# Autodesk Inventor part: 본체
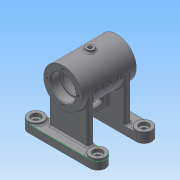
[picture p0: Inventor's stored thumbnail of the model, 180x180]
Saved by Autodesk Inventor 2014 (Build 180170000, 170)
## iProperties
Created: 2015-11
Part Number: 본체
Material: 일반
Document SubType Name: Modeling
Designer: net
Density: 1 g/cm^3
Appearance: 기본값
Author: net
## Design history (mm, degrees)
sketch "스케치1"
  geometry: L1 (-40, -10)-(40, -10); L2 (40, 10)-(-40, 10); L3 (-40, -10)-(35.294, 8.824); L4 (40, -10)-(-40, 10); C1 r 3 at (-40, 0); C2 r 3 at (40, 0); A1 r 10 centre (-40, 0) between (-40, 10) and (-40, -10); A2 r 10 centre (40, 0) between (40, -10) and (40, 10); 1 further point
  constraints: 8 end point, 4 centre point, 4 point on circle, 2 coincident, 2 equal radius, 2 parallel, 2 tangent, 1 horizontal, 1 midpoint, 1 point on line
  dimensions: "d15" = 100 dimension on A2 A1; "d18" = 10 radius of A1; "d19" = 6 diameter of C1; "d20" = 151.928 deg angle of L3 L4; "d21" = 17.12016 distance from line of L3.end L4
extrude "돌출1" new body sketch "스케치1" distance "d22" = 10; taper "d23" = 0 deg
sketch "스케치2"
  geometry: C1 r 3 at (40, 0) reference; C2 r 3 at (-40, 0) reference; C3 r 10 at (-40, 0); C4 r 10 at (40, 0); A1 r 10 centre (-40, 0) between (-40, 10) and (-40, -10) reference; A2 r 10 centre (40, 0) between (40, -10) and (40, 10) reference; 1 further point
  constraints: 2 centre point, 2 coincident
  dimensions: "d24" = 20 diameter of C3; "d25" = 20 diameter of C4
extrude "돌출2" join sketch "스케치2" distance "d26" = 3; taper "d27" = 0 deg
sketch "스케치3"
  geometry: L1 (80, 0)-(0, 0) reference; L2 (15, 68)-(65, 68); L3 (65, 68)-(65, 0); L4 (65, 0)-(15, 0); L5 (15, 0)-(15, 68); 2 further points
  constraints: 8 end point, 2 midpoint, 2 parallel, 1 horizontal, 1 perpendicular
  dimensions: "d28" = 50 distance of L3.end L4.end; "d29" = 68 distance between parallel lines of L4 L2
extrude "돌출3" join sketch "스케치3" distance "d30" = 8; taper "d31" = 0 deg
sketch "스케치4"
  geometry: L1 (-40, -50)-(40, -50); L2 (40, -50)-(40, -70); L3 (40, -70)-(-40, -70); L4 (-40, -70)-(-40, -50); C1 r 3 at (-40, -60); C2 r 3 at (40, -60); 3 further points
  constraints: 8 end point, 2 centre point, 2 coincident, 2 midpoint, 2 parallel, 2 vertical alignment, 1 equal radius, 1 horizontal, 1 perpendicular, 4 other
  dimensions: "d34" = 80 distance between parallel lines of L2 L4; "d35" = 20 distance between parallel lines of L3 L1; "d36" = 40 distance from line of point (0, 0) L4 (= 0.5 x d34); "d37" = 50 distance from line of L1 point (0, 0); "d38" = 6 diameter of C1
extrude "돌출4" join sketch "스케치4" distance "d39" = 10; taper "d40" = 0 deg
sketch "스케치5"
  geometry: L1 (-40, -70)-(40, -70) reference; L2 (40, -50)-(-40, -50) reference; A1 r 10 centre (40, -60) between (40, -70) and (40, -50) reference; A2 r 10 centre (-40, -60) between (-40, -50) and (-40, -70) reference; 1 further point
extrude "돌출5" join sketch "스케치4" distance "d41" = 13; taper "d42" = 0 deg
extrude "돌출6" cut sketch "스케치4" stored distance "d43" = 13; taper "d44" = 0 deg
sketch "스케치6"
  geometry: L1 (0, 0)-(80, 0) reference; L2 (15, -68)-(65, -68); L3 (65, -68)-(65, 0); L4 (65, 0)-(15, 0); L5 (15, 0)-(15, -68); 1 further point
  constraints: 8 end point, 2 parallel, 1 horizontal, 1 perpendicular, 1 point on line
  dimensions: "d45" = 50 distance between parallel lines of L3 L5; "d46" = 68 distance between parallel lines of L2 L1; "d47" = 25 distance from line of point (40, 0) L5 (= 0.5 x d45)
extrude "돌출7" join sketch "스케치6" distance "d48" = 8; taper "d49" = 0 deg
node "작업 평면1"
node "작업 평면2"
sketch "스케치8"
  geometry: L1 (0, -40)-(0, -48) reference; L2 (0, 0)-(0, 8) reference; L3 (-25, -55)-(0, -55); L4 (0, -55)-(0, 15); L5 (0, 15)-(-25, 15); L6 (-25, 15)-(-25, -55); L7 (45, 0)-(45, -40) reference; L8 (45, -20)-(-11.349, -20); L9 (68, -60)-(68, -40) reference; L10 (68, 0)-(68, 20) reference; 2 further points
  constraints: 10 end point, 2 horizontal, 2 midpoint, 2 parallel, 1 perpendicular, 1 point on line
  dimensions: "d60" = 70 distance of L5.end L3.start; "d61" = 25 distance of L3.start L3.end; "d62" = 56.34938 distance of L8.start L8.end; "d64" = 68 distance between parallel lines of L10 L4
revolve "회전1" sketch "스케치8" stored, may be unused: angle "d65" = 90 deg
node "작업 평면3"
sketch "스케치10"
  geometry: L1 (-83, -7)-(-83, 63) reference; L2 (-33, -7)-(-33, 63) reference; L3 (-33, -7)-(-83, -7) reference; L4 (-58, -7)-(-58, 63); L5 (-33, 63)-(-83, 63) reference; L6 (-58, 7)-(-79, 7); L7 (-79, 7)-(-79, 49); L8 (-79, 49)-(-58, 49); 1 further point
  constraints: 8 end point, 2 horizontal, 2 midpoint, 2 point on line, 1 vertical
  dimensions: "d72" = 42 distance between parallel lines of L8 L6; "d73" = 14 distance between parallel lines of L6 L3; "d74" = 42 diameter of L7 L4
revolve "회전2" sketch "스케치10" stored, may be unused: angle "d75" = 90 deg
hole "구멍1" diameter "d78" = 28; stored, may be unused: countersink angle "d82" = 90 deg, drill point angle "d84" = 0 deg; dims "d76" = 10, "d77" = 10, "d79" = 6, "d80" = 32, "d81" = 12, "d83" = 14
hole "구멍2" diameter "d87" = 28; stored, may be unused: countersink angle "d91" = 90 deg, drill point angle "d93" = 0 deg; dims "d85" = 10, "d86" = 10, "d88" = 6, "d89" = 32, "d90" = 12, "d92" = 14
node "작업 평면4"
sketch "스케치11"
  geometry: L1 (0, -50)-(0, -10) reference; C1 r 5 at (0, -30); 1 further point
  constraints: 1 centre point, 1 midpoint
  dimensions: "d95" = 10 diameter of C1
extrude "돌출9" join sketch "스케치11" stored distance "d96" = 8; taper "d97" = 0 deg
node "작업 평면5"
sketch "스케치12"
  geometry: L1 (40, -68)-(15, -68); L2 (40, -68)-(15.751, -54); C1 r 16 at (40, -68) reference; 1 further point
  constraints: 4 end point, 1 horizontal, 1 horizontal alignment
  dimensions: "d98" = 30 deg angle of L2 L1; "d99" = 28 distance of L1.start L2.end
  node "투영된 루프4"
node "작업 평면6"
sketch "스케치13"
  geometry: L1 (-35, 25)-(-35, -25) reference; C1 r 6 at (0, 0); 1 further point
  constraints: 1 centre point
  dimensions: "d100" = 12 diameter of C1; "d101" = 66.09085 distance of C1.centre point (-30, -58.89); "d102" = 35 distance from line of C1.centre L1
extrude "돌출10" join sketch "스케치13" stored distance "d103" = 8; taper "d104" = 0 deg
hole "구멍3" diameter "d107" = 4.917; stored, may be unused: countersink angle "d111" = 90 deg, drill point angle "d113" = 118 deg; dims "d105" = 10, "d106" = 10, "d108" = 6, "d109" = 32, "d110" = 12, "d112" = 14
hole "구멍4" diameter "d116" = 4.917; stored, may be unused: countersink angle "d120" = 90 deg, drill point angle "d122" = 118 deg; dims "d114" = 10, "d115" = 10, "d117" = 6, "d118" = 32, "d119" = 12, "d121" = 14
sketch "스케치14"
  geometry: C1 r 16 at (0, 0) reference; 2 further points
  constraints: 1 vertical alignment
  dimensions: "d123" = 20 distance of C1.centre point (0, 20)
hole "구멍5" sketch "스케치14" at (0, 20) diameter "d124" = 3.242; stored, may be unused: countersink angle "d128" = 90 deg, drill point angle "d130" = 118 deg; dims "d125" = 8, "d126" = 32, "d127" = 12, "d129" = 10
node "작업 평면7"
sketch "스케치15"
  geometry: C1 r 3 at (0, 0) reference; C2 r 10 at (0, 0) reference; 1 further point
hole "구멍6" diameter "d136" = 12; stored, may be unused: countersink angle "d140" = 90 deg, drill point angle "d142" = 0 deg; dims "d134" = 10, "d135" = 10, "d137" = 8, "d138" = 32, "d139" = 12, "d141" = 4
hole "구멍7" diameter "d145" = 12; stored, may be unused: countersink angle "d149" = 90 deg, drill point angle "d151" = 0 deg; dims "d143" = 10, "d144" = 10, "d146" = 8, "d147" = 32, "d148" = 12, "d150" = 4
hole "구멍8" diameter "d154" = 12; stored, may be unused: countersink angle "d158" = 90 deg, drill point angle "d160" = 0 deg; dims "d152" = 10, "d153" = 10, "d155" = 8, "d156" = 32, "d157" = 12, "d159" = 4
hole "구멍9" diameter "d163" = 12; stored, may be unused: countersink angle "d167" = 90 deg, drill point angle "d169" = 0 deg; dims "d161" = 10, "d162" = 10, "d164" = 8, "d165" = 32, "d166" = 12, "d168" = 4
fillet "모깎기1" dims "d170" = 2
fillet "모깎기2" dims "d171" = 2
node "작업 평면8"
sketch "스케치16"
  geometry: L1 (-48.202, 6)-(0, 6) reference; L2 (10, 59)-(10, 53) reference; L3 (10, -1)-(10, -7) reference; L4 (0, 46)-(-48.202, 46) reference; L5 (-35, 6)-(-13, 6); L6 (-13, 6)-(-13, 46); L7 (-13, 46)-(-35, 46); L8 (-35, 46)-(-35, 6); L9 (10, 46)-(10, 66) reference; L10 (-23, 18)-(-23, 34); L11 (-19.5, 18)-(-19.5, 34); L12 (-26.5, 34)-(-26.5, 18); A1 r 3.5 centre (-23, 18) between (-26.5, 18) and (-19.5, 18); A2 r 3.5 centre (-23, 34) between (-19.5, 34) and (-26.5, 34); 2 further points
  constraints: 16 end point, 4 point on circle, 4 tangent, 3 parallel, 2 centre point, 2 point on line, 1 horizontal, 1 midpoint, 1 perpendicular, 1 vertical
  dimensions: "d190" = 23 distance between parallel lines of L9 L6; "d191" = 22 distance between parallel lines of L6 L8; "d192" = 3.5 radius of A2; "d193" = 23 dimension on A2 A1; "d194" = 20 distance from line of point (-23, 26) L5; "d195" = 33 distance between parallel lines of L9 L10
extrude "돌출11" join sketch "스케치16" stored distance "d196" = 8; taper "d197" = 0 deg
fillet "모깎기4" dims "d198" = 2
fillet "모깎기5" dims "d199" = 2
fillet "모깎기6" dims "d200" = 2
fillet "모깎기7" dims "d201" = 2
fillet "모깎기8" dims "d202" = 2
fillet "모깎기9" dims "d203" = 2
fillet "모깎기10" dims "d204" = 3
fillet "모깎기11" dims "d205" = 0.3
node "작업 평면10"
sketch "스케치17"
  geometry: L1 (-65, 93)-(5, 93) reference; L2 (-65, 43)-(-65, 93) reference; 2 further points
  constraints: 1 other
  dimensions: "d208" = 25 distance from line of point (-30, 68) L1; "d209" = 35 distance from line of point (-30, 68) L2
feature "엠보싱1" sketch "스케치17" dims "d210" = 0.5, "d211" = 0
chamfer "모따기1" distance "d212" = 1; stored, may be unused: second distance "d213" = 2, angle "d214" = 45 deg
node "솔리드1"
pattern_circular "원형 패턴1" dims angle "d132" = 360 deg
mirror "대칭1"
other parameters: "d94" = -96, "d207" = 26
